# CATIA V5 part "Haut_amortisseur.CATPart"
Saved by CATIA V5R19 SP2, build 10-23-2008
Part number: Haut_amortisseur
Bounding box of the stored display mesh (mm): x -24 to 24, y -674.825 to -627.175, z 335 to 485
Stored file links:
  G:\EU_thinkMotion\CFAO_2010\MMS_groupe3\MMS_groupe3\pmayet\pmayet_assemblage_animation\pmayet_assemblage_animation\Haut_amortisseur.CATPart
  G:\EU_thinkMotion\CFAO_2010\MMS_groupe3\MMS_groupe3\pmayet\pmayet_assemblage_animation\pmayet_assemblage_animation\pmayet_assemblage_animation.CATProduct
  G:\EU_thinkMotion\CFAO_2010\MMS_groupe3\MMS_groupe3\pmayet\pmayet_assemblage_animation\pmayet_assemblage_animation\Bas_amortisseur.CATPart
  G:\EU_thinkMotion\CFAO_2010\MMS_groupe3\MMS_groupe3\pmayet\pmayet_assemblage_animation\pmayet_assemblage_animation\Squelette_amortisseur.CATPart
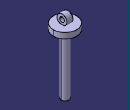
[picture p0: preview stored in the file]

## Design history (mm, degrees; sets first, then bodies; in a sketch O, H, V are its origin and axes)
Parameters
  Epaisseur_amortisseur = 6 mm
  Rayon_trou_amortisseur = 5 mm
  Rayon_tige_amortisseur = 8 mm
  Hauteur_amortisseur = 80 mm
Set1
  Plane1: linked copy from another document
  Point1 "Point.20_amortisseur": linked copy from another document
  Plane2: linked copy from another document
Body1 (main body)
  Sketch1 on Plane1, origin (0, 0, 0), H (0, 1, 0), V (0, 0, 1)
    circle A1 centre (-651, 475) radius 5
    point P1 (-651, 475)
    reference projected point E1 (-651, 475) from Point1
    arc A2 centre (-651, 475) radius 10 from (-646, 466.3397) to (-656, 466.3397) ccw
    point P2 (-651, 475)
    point P3 (-646, 466.3397)
    point P4 (-656, 466.3397)
    point P5 (-656, 466.3397)
    line L1 (-646, 466.3397) -> (-646, 461.3397)
    line L2 (-646, 461.3397) -> (-656, 461.3397)
    line L3 (-656, 461.3397) -> (-656, 466.3397)
    point P6 (-646, 466.3397)
    reference projected point E2 (-651, 475) from Point1
    reference projected point E3 (-651, 475) from Point1
    reference projected point E4 (-651, 475) from Point1
    distance A1 P1 = 5 {= Rayon_trou_amortisseur}
    radius A2 = 10 {= Rayon_trou_amortisseur *2}
    distance L1 E3 = 5 {= Rayon_trou_amortisseur}
    distance E4 L3 = 5 {= Rayon_trou_amortisseur}
    distance P3 P6 = 0
    distance P4 P5 = 0
    length L1 = 5 {= Rayon_trou_amortisseur}
    coincidence: P1 E1, P2 E2
    horizontal: L2 H
    vertical: L1 V, L3 V
  Pad1: profile Sketch1, direction (1, 0, 0), length 6 {= Epaisseur_amortisseur}, mirrored extent
  Sketch2 on face of Pad1 from Sketch1.L2, origin (0, 0, 461.3397), H (1, 0, 0), V (0, -1, 0)
    circle A1 centre (0, 651) radius 24
    point P1 (0, 651)
    reference projected point E1 (0, 651) from Point1
    distance A1 P1 = 24 {= Rayon_tige_amortisseur *3}
    coincidence: E1 P1
  Pad2: profile Sketch2, direction (0, 0, -1), up to Plane2, opposite side length 5 {= Rayon_trou_amortisseur}
  Sketch3 on end face of Pad2, origin (0, 0, 455), H (1, 0, 0), V (0, -1, 0)
    circle A1 centre (0, 651) radius 8
    point P1 (0, 651)
    reference projected point E1 (0, 651) from Point1
    distance A1 P1 = 8 {= Rayon_tige_amortisseur}
    coincidence: E1 P1
  Pad3: profile Sketch3, direction (0, 0, -1), length 120 {= Hauteur_amortisseur *1.5}
Relations
  Pad2.FirstLimit.Length = Rayon_trou_amortisseur (deactivated)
